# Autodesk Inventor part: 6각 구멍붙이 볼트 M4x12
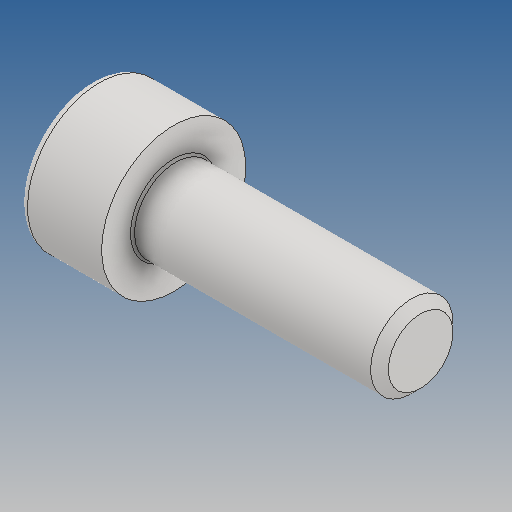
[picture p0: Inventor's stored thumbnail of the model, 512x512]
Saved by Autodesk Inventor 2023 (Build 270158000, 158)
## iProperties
Created: 2025-03
Part Number: 6각 구멍붙이 볼트 M4x12
Material: 스테인리스강
Description: 6각 소켓 머리 캡 나사
Document SubType Name: Modeling
Designer: Admin
Density: 8.08 g/cm^3
Appearance: 기본값
Author: jhkim
Sending System: Autodesk Inventor 2025
Preprocessor: ST-DEVELOPER v20
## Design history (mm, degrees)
node "6각 구멍붙이 볼트 M4x121"
node "솔리드1"
body "Solid1"
